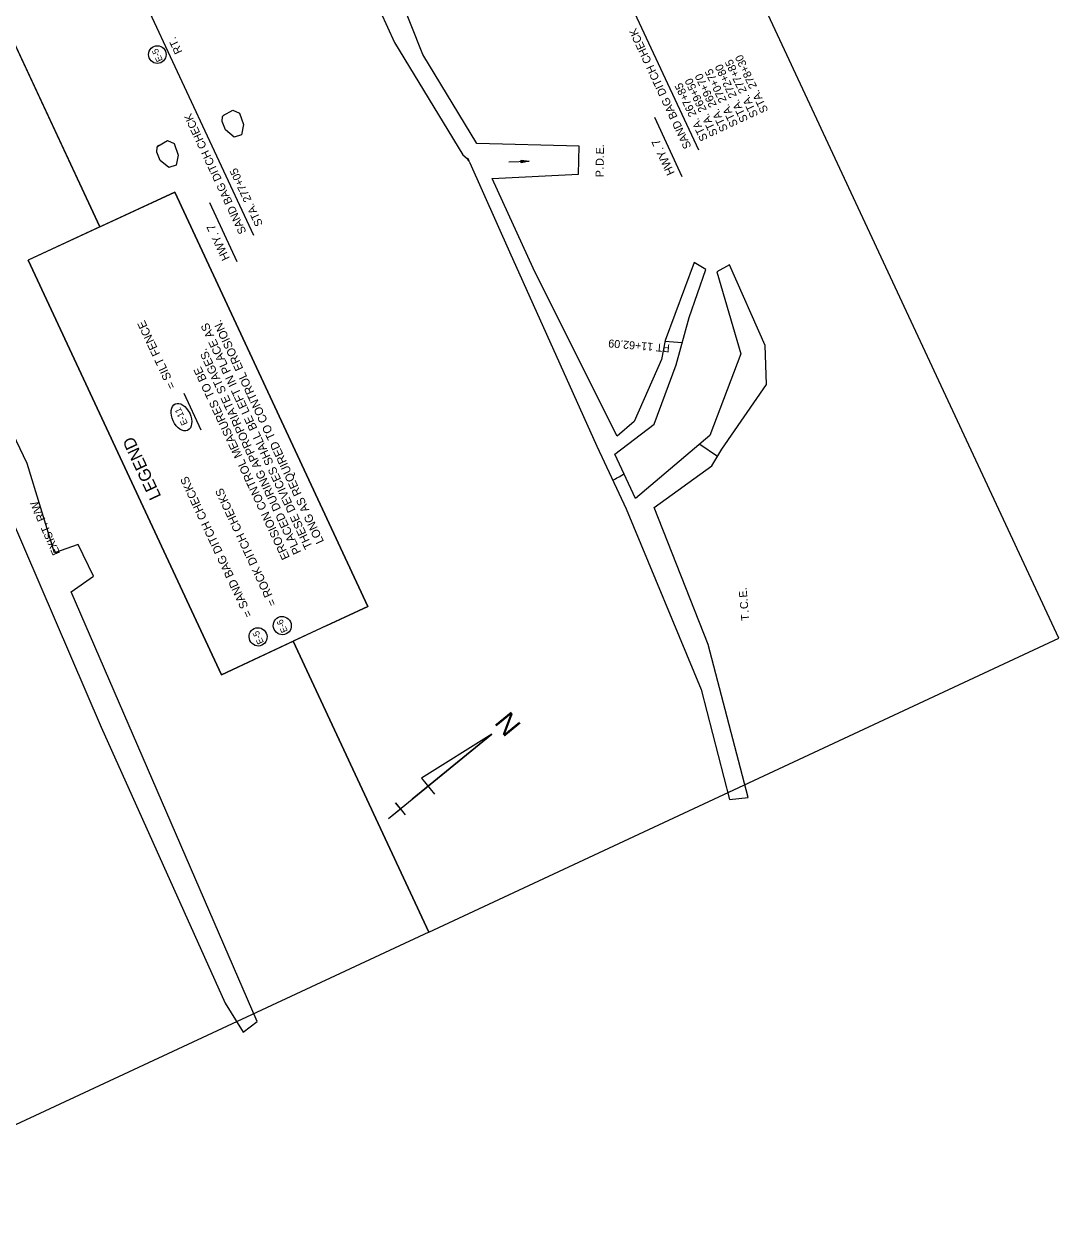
# Model space of a CAD drawing. Extents: x 964229 to 965790, y 1899262 to 1901149.
# Drawn here: x 965014 to 965790, y 1899262 to 1900163 of the extents above; entities that cross this region are included whole.
import ezdxf

# ---------------------------------------------------------------- set-up
doc = ezdxf.new("R2010")
doc.units = 0
for name, color, linetype in [('1', 7, 'Continuous'), ('43', 7, 'Continuous'), ('44', 7, 'Continuous'), ('63', 7, 'Continuous'), ('Level 1', 7, 'Continuous'), ('Level 44', 7, 'Continuous'), ('NO PLOT', 7, 'Continuous'), ('R_Draft', 7, 'Continuous'), ('R_Horz Alg', 7, 'Continuous'), ('R_Horz Alg Annot', 7, 'Continuous'), ('S_TREE', 7, 'Continuous')]:
    doc.layers.add(name, color=color, linetype=linetype)

msp = doc.modelspace()

# ---------------------------------------------------------------- linework, layer by layer
at = {"layer": '1'}
for p, q in [((965070.98, 1900011.03), (964950.03, 1900270.4)), ((965126.95, 1900037.14), (965017.24, 1899985.98)), ((965162.05, 1899675.42), (965017.24, 1899985.98)), ((965241.02, 1899712.24), (965162.05, 1899675.42)), ((965317.44, 1899482.49), (965215.79, 1899700.48))]:
    msp.add_line(p, q, dxfattribs=at)
msp.add_lwpolyline([(965241.02, 1899712.24), (965271.77, 1899726.58), (965126.95, 1900037.14)], dxfattribs=at)
msp.add_circle((965113.95, 1900140.18), 6.61, dxfattribs=at)
at = {"layer": '43'}
for p, q in [((965386.67, 1900058.98), (965386.6, 1900061.13)), ((965386.6, 1900061.13), (965392.71, 1900060.24)), ((965392.71, 1900060.24), (965386.67, 1900058.98))]:
    msp.add_line(p, q, dxfattribs=at)
msp.add_lwpolyline([(965377.53, 1900059.77), (965392.71, 1900060.24)], dxfattribs=at)
at = {"layer": '44'}
for p, q in [((965519.81, 1900068.44), (965417.95, 1900286.86)), ((965186.28, 1900004.53), (965084.43, 1900222.96)), ((965507.41, 1900048.66), (965486.77, 1900092.93)), ((965173.89, 1899984.76), (965153.24, 1900029.02))]:
    msp.add_line(p, q, dxfattribs=at)
at = {"layer": '63'}
for p, q in [((965287.19, 1899567.51), (965364.58, 1899630.84)), ((965364.58, 1899630.84), (965305.05, 1899582.13)), ((965364.58, 1899630.84), (965312.08, 1899597.82)), ((965312.08, 1899597.82), (965321.82, 1899585.92)), ((965287.19, 1899567.51), (965305.05, 1899582.13)), ((965287.19, 1899567.51), (965296.12, 1899574.82)), ((965296.12, 1899574.82), (965292.46, 1899579.28)), ((965292.46, 1899579.28), (965299.77, 1899570.35))]:
    msp.add_line(p, q, dxfattribs=at)
at = {"layer": 'Level 1'}
for centre, major_axis, ratio in [((965132.03, 1899868.45), (-4.63, 9.93), 0.622952), ((965207.6, 1899712.22), (2.91, -6.24), 0.97521), ((965189.47, 1899703.76), (2.91, -6.24), 0.97521)]:
    msp.add_ellipse(centre, major_axis=major_axis, ratio=ratio, dxfattribs=at)
at = {"layer": 'Level 44'}
msp.add_lwpolyline([(965146.86, 1899858.74), (965134.12, 1899886.04)], dxfattribs=at)
at = {"layer": 'NO PLOT'}
for points in [[(965789.77, 1899702.74), (965115.54, 1901148.63), (964643.21, 1900928.38), (964770.42, 1900655.58), (964831.6, 1900684.11), (965011.21, 1900298.93), (964950.03, 1900270.4), (965070.98, 1900011.03), (965126.95, 1900037.14), (965271.77, 1899726.58), (965215.79, 1899700.48), (965317.44, 1899482.49)], [(965789.77, 1899702.74), (965115.54, 1901148.63), (964643.21, 1900928.38), (964770.42, 1900655.58), (964831.6, 1900684.11), (965011.21, 1900298.93), (964950.03, 1900270.4), (965070.98, 1900011.03), (965126.95, 1900037.14), (965271.77, 1899726.58), (965215.79, 1899700.48), (965317.44, 1899482.49)], [(965789.77, 1899702.74), (965115.54, 1901148.63), (964643.21, 1900928.38), (964770.42, 1900655.58), (964831.6, 1900684.11), (965011.21, 1900298.93), (964950.03, 1900270.4), (965070.98, 1900011.03), (965126.95, 1900037.14), (965271.77, 1899726.58), (965215.79, 1899700.48), (965317.44, 1899482.49)], [(965789.77, 1899702.74), (965115.54, 1901148.63), (964643.21, 1900928.38), (964770.42, 1900655.58), (964831.6, 1900684.11), (965011.21, 1900298.93), (964950.03, 1900270.4), (965070.98, 1900011.03), (965126.95, 1900037.14), (965271.77, 1899726.58), (965215.79, 1899700.48), (965317.44, 1899482.49)], [(964845.11, 1899262.24), (964344.7, 1900335.36), (964389.48, 1900356.24), (964306.73, 1900533.69), (964319.96, 1900539.86), (964228.89, 1900735.17), (964643.21, 1900928.38), (964770.42, 1900655.58), (964700.63, 1900623.04), (964880.25, 1900237.86), (964950.03, 1900270.4), (965070.98, 1900011.03), (965017.24, 1899985.98), (965162.05, 1899675.42), (965215.79, 1899700.48), (965317.44, 1899482.49)], [(964845.11, 1899262.24), (964344.7, 1900335.36), (964389.48, 1900356.24), (964306.73, 1900533.69), (964319.96, 1900539.86), (964228.89, 1900735.17), (964643.21, 1900928.38), (964770.42, 1900655.58), (964700.63, 1900623.04), (964880.25, 1900237.86), (964950.03, 1900270.4), (965070.98, 1900011.03), (965017.24, 1899985.98), (965162.05, 1899675.42), (965215.79, 1899700.48), (965317.44, 1899482.49)], [(964845.11, 1899262.24), (964344.7, 1900335.36), (964389.48, 1900356.24), (964306.73, 1900533.69), (964319.96, 1900539.86), (964228.89, 1900735.17), (964643.21, 1900928.38), (964770.42, 1900655.58), (964700.63, 1900623.04), (964880.25, 1900237.86), (964950.03, 1900270.4), (965070.98, 1900011.03), (965017.24, 1899985.98), (965162.05, 1899675.42), (965215.79, 1899700.48), (965317.44, 1899482.49)], [(964845.11, 1899262.24), (964344.7, 1900335.36), (964389.48, 1900356.24), (964306.73, 1900533.69), (964319.96, 1900539.86), (964228.89, 1900735.17), (964643.21, 1900928.38), (964770.42, 1900655.58), (964700.63, 1900623.04), (964880.25, 1900237.86), (964950.03, 1900270.4), (965070.98, 1900011.03), (965017.24, 1899985.98), (965162.05, 1899675.42), (965215.79, 1899700.48), (965317.44, 1899482.49)], [(965347.31, 1900060.65), (965346.28, 1900062.47), (965346.24, 1900062.45), (965347.28, 1900060.63)]]:
    msp.add_lwpolyline(points, close=True, dxfattribs=at)
for points in [[(965176.25, 1900402.21), (965291.71, 1900149.32), (965342.96, 1900065.1), (965346.17, 1900062.34), (965346.6, 1900062.65), (965346.62, 1900062.57), (965347.35, 1900060.46), (965347.33, 1900060.4), (965347.59, 1900060.06), (965348.08, 1900059.15), (965377.94, 1899992.37), (965443.26, 1899846.6), (965465.34, 1899799.73), (965521.63, 1899664.21), (965542.72, 1899581.94), (965556.69, 1899583.34), (965526.85, 1899697.97), (965486.39, 1899800.6), (965529.54, 1899831.99), (965537.16, 1899844.35), (965570.5, 1899893), (965569.59, 1899922.15), (965542.83, 1899982.57), (965533.26, 1899977.4), (965551.42, 1899915.79), (965528.16, 1899854.59), (965472.29, 1899807.41), (965456.78, 1899840.67), (965486.4, 1899863.29), (965502.76, 1899907.54), (965512.6, 1899943.12), (965525.02, 1899979.2), (965516.3, 1899984.29), (965494.55, 1899925.9), (965491.73, 1899911.55), (965471.45, 1899865.12), (965458.58, 1899854.19), (965398.05, 1899974.93), (965395.62, 1899980.14), (965365.04, 1900047.23), (965429.7, 1900050.61), (965430.14, 1900071.59), (965353.48, 1900073.53), (965312.89, 1900140.18), (965294.07, 1900188.1)], [(964743.2, 1900380.79), (964921.35, 1899985.44), (965071.82, 1899636.13), (965164.72, 1899429.12), (965178.4, 1899407.57), (965188.68, 1899415.47), (965049.43, 1899737.41), (965066.12, 1899749.34), (965054.6, 1899772.93), (965036.81, 1899766.7), (965016.41, 1899833.74), (964918.01, 1900039.22), (964930.54, 1900052.3), (964920.78, 1900078.79), (964905.36, 1900075.22), (964854.38, 1900212.3)]]:
    msp.add_lwpolyline(points, dxfattribs=at)
at = {"layer": 'R_Horz Alg'}
msp.add_arc((965399.28, 1899932.96), 125, 296.5924, 301.02, dxfattribs=at)
at = {"layer": 'R_Horz Alg Annot'}
for points in [[(965507.32, 1899924.01), (965494.25, 1899925.09)], [(965520.7, 1899848.28), (965533.91, 1899839.07)]]:
    msp.add_lwpolyline(points, dxfattribs=at)
at = {"layer": 'S_TREE'}
for points in [[(965163.32, 1900094.45), (965170.46, 1900098.57), (965175.51, 1900096.27), (965178.42, 1900087.66), (965177.13, 1900080.14), (965171.56, 1900078.38), (965164.99, 1900083.71), (965162.58, 1900089.97), (965162.87, 1900093.66), (965163.96, 1900094.98)], [(965163.32, 1900094.45), (965170.46, 1900098.57), (965175.51, 1900096.27), (965178.42, 1900087.66), (965177.13, 1900080.14), (965171.56, 1900078.38), (965164.99, 1900083.71), (965162.58, 1900089.97), (965162.87, 1900093.66), (965163.96, 1900094.98)], [(965114.38, 1900071.63), (965121.52, 1900075.75), (965126.57, 1900073.45), (965129.48, 1900064.84), (965128.19, 1900057.32), (965122.62, 1900055.56), (965116.05, 1900060.89), (965113.64, 1900067.15), (965113.93, 1900070.84), (965115.01, 1900072.16)]]:
    msp.add_lwpolyline(points, dxfattribs=at)

# ---------------------------------------------------------------- texts
at = {"layer": '1'}
msp.add_text('E-5 ', height=4.8, rotation=115, dxfattribs=at).set_placement((965118.17, 1900136.07))
at = {"layer": '44'}
for s, height, p in [('SAND BAG DITCH CHECK', 6, (965514.38, 1900071.19)), ('RT.', 6, (965132.86, 1900142.22)), ('STA. 278+30', 6, (965572.04, 1900098.08)), ('STA. 270+75', 6, (965549.39, 1900087.52)), ('STA. 272+80', 6, (965556.94, 1900091.04)), ('STA. 277+85', 6, (965564.49, 1900094.56)), ('STA. 269+50', 6, (965534.32, 1900080.49)), ('STA. 269+70', 6, (965541.87, 1900084.01)), ('STA. 267+85', 6, (965526.77, 1900076.97)), ('SAND BAG DITCH CHECK', 6, (965180.85, 1900007.29)), ('HWY. 7', 6.25, (965501.94, 1900051.45)), ('STA. 277+05', 6, (965193.24, 1900013.07)), ('HWY. 7', 6.25, (965168.41, 1899987.55))]:
    msp.add_text(s, height=height, rotation=115, dxfattribs=at).set_placement(p)
at = {"layer": '63'}
msp.add_text('N', height=15.38, rotation=309.29267, dxfattribs=at).set_placement((965365.97, 1899639.26))
at = {"layer": 'Level 1'}
for s, height, p in [('= SILT FENCE', 6.25, (965127.79, 1899891.22)), ('LONG AS REQUIRED TO CONTROL EROSION.', 6.25, (965238.99, 1899775.26)), ('THESE DEVICES SHALL BE LEFT IN PLACE AS ', 6.25, (965230.46, 1899771.28)), ('PLACED DURING APPROPRIATE STAGES. ', 6.25, (965221.93, 1899767.3)), ('EROSION CONTROL MEASURES TO BE', 6.25, (965213.4, 1899763.33)), ('E-11 ', 4.876, (965136.91, 1899863.67)), ('= SAND BAG DITCH CHECKS', 6.25, (965185.32, 1899720.06)), ('= ROCK DITCH CHECKS', 6.25, (965203.44, 1899728.52)), ('E-6 ', 4.876, (965211.82, 1899708.2)), ('E-5 ', 4.876, (965193.87, 1899699.59))]:
    msp.add_text(s, height=height, rotation=115.00001, dxfattribs=at).set_placement(p)
at = {"layer": 'Level 44'}
msp.add_text('LEGEND', height=9.143, rotation=115.00001, dxfattribs=at).set_placement((965117.06, 1899809.06))
at = {"layer": 'R_Draft'}
for s, rotation, p in [('E', 89.12954, (965448.65, 1900065.34)), ('.', 89.12954, (965448.74, 1900070.73)), ('D', 89.12954, (965448.52, 1900056.75)), ('.', 89.12954, (965448.61, 1900062.41)), ('P', 89.12954, (965448.39, 1900048.15)), ('.', 89.12954, (965448.48, 1900053.82)), ('EXIST. R/W', 113.66592, (965041.29, 1899766.52)), ('E', 94.92297, (965556.22, 1899733.42)), ('.', 94.92297, (965555.76, 1899738.79)), ('C', 94.92297, (965556.96, 1899724.86)), ('.', 94.92297, (965556.48, 1899730.5)), ('T', 94.92297, (965557.72, 1899716.1)), ('.', 94.92297, (965557.21, 1899721.94))]:
    msp.add_text(s, height=6, rotation=rotation, dxfattribs=at).set_placement(p)
at = {"layer": 'R_Horz Alg Annot'}
msp.add_text('PT 11+62.09', height=6, rotation=175.26469, dxfattribs=at).set_placement((965498.29, 1899922.93))

doc.saveas('drawing.dxf')
